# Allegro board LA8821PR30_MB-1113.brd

Outline 233.5 x 89.85 mm; copper layers: TOP, GND1, IN1, GND2, IN2, GND3, VCC, IN3, GND4, IN4, GND5, BOTTOM. Coordinates in mm from the lower left corner of the outline.

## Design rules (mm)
net group SPACING-15-20: nets DMI_IRCOMP RBIAS_CPY
net group 4: nets +1.35V +VREFCA_B GND
net group 10: nets +0.675VS +VREFCA_A +VREFDQ_A +VREFDQ_B
net group DDR_CLK_16_25: nets M_CLK_DDR0 M_CLK_DDR2 M_CLK_DDR#0 M_CLK_DDR#2
net group DDR_CMD_6_16_25: nets DDR3_DRAMRST# DDR_A_BS0 DDR_A_BS1 DDR_A_BS2 DDR_A_CAS# DDR_A_MA0 DDR_A_MA1 DDR_A_MA2 DDR_A_MA3 DDR_A_MA4 DDR_A_MA5 DDR_A_MA6 DDR_A_MA7 DDR_A_MA8 DDR_A_MA9 DDR_A_MA10 DDR_A_MA11 DDR_A_MA12 DDR_A_MA13 DDR_A_MA14 DDR_A_MA15 DDR_A_RAS# DDR_A_WE# DDR_B_BS0 DDR_B_BS1 DDR_B_BS2 DDR_B_CAS# DDR_B_MA0 DDR_B_MA1 DDR_B_MA2 DDR_B_MA3 DDR_B_MA4 DDR_B_MA5 DDR_B_MA6 DDR_B_MA7 DDR_B_MA8 DDR_B_MA9 DDR_B_MA10 DDR_B_MA11 DDR_B_MA12 DDR_B_MA13 DDR_B_MA14 DDR_B_MA15 DDR_B_RAS# DDR_B_WE#
net group DDR_CTRL_6_16_25: nets DDR_A_CKE0 DDR_A_CS0# DDR_B_CKE0 DDR_B_CS0# M_ODT0 M_ODT2
net group DDR_DQ_6_16_25: nets DDR_A_D0 DDR_A_D1 DDR_A_D2 DDR_A_D3 DDR_A_D4 DDR_A_D5 DDR_A_D6 DDR_A_D7 DDR_A_D8 DDR_A_D9 DDR_A_D10 DDR_A_D11 DDR_A_D12 DDR_A_D13 DDR_A_D14 DDR_A_D15 DDR_A_D16 DDR_A_D17 DDR_A_D18 DDR_A_D19 DDR_A_D20 DDR_A_D21 DDR_A_D22 DDR_A_D23 DDR_A_D24 DDR_A_D25 DDR_A_D26 DDR_A_D27 DDR_A_D28 DDR_A_D29 DDR_A_D30 DDR_A_D31 DDR_A_D32 DDR_A_D33 DDR_A_D34 DDR_A_D35 DDR_A_D36 DDR_A_D37 DDR_A_D38 DDR_A_D39 DDR_A_D40 DDR_A_D41 DDR_A_D42 DDR_A_D43 DDR_A_D44 DDR_A_D45 DDR_A_D46 DDR_A_D47 DDR_A_D48 DDR_A_D49 DDR_A_D50 DDR_A_D51 DDR_A_D52 DDR_A_D53 DDR_A_D54 DDR_A_D55 DDR_A_D56 DDR_A_D57 DDR_A_D58 DDR_A_D59 DDR_A_D60 DDR_A_D61 DDR_A_D62 DDR_A_D63 DDR_B_D0 DDR_B_D1 DDR_B_D2 DDR_B_D3 DDR_B_D4 DDR_B_D5 DDR_B_D6 DDR_B_D7 DDR_B_D8 DDR_B_D9 DDR_B_D10 DDR_B_D11 DDR_B_D12 DDR_B_D13 DDR_B_D14 DDR_B_D15 DDR_B_D16 DDR_B_D17 DDR_B_D18 DDR_B_D19 DDR_B_D20 DDR_B_D21 DDR_B_D22 DDR_B_D23 DDR_B_D24 DDR_B_D25 DDR_B_D26 DDR_B_D27 DDR_B_D28 DDR_B_D29 DDR_B_D30 DDR_B_D31 DDR_B_D32 DDR_B_D33 DDR_B_D34 DDR_B_D35 DDR_B_D36 DDR_B_D37 DDR_B_D38 DDR_B_D39 DDR_B_D40 DDR_B_D41 DDR_B_D42 DDR_B_D43 DDR_B_D44 DDR_B_D45 DDR_B_D46 DDR_B_D47 DDR_B_D48 DDR_B_D49 DDR_B_D50 DDR_B_D51 DDR_B_D52 DDR_B_D53 DDR_B_D54 DDR_B_D55 DDR_B_D56 DDR_B_D57 DDR_B_D58 DDR_B_D59 DDR_B_D60 DDR_B_D61 DDR_B_D62 DDR_B_D63
net group DDR_DQS_16_25: nets DDR_A_DQS0 DDR_A_DQS1 DDR_A_DQS2 DDR_A_DQS3 DDR_A_DQS4 DDR_A_DQS5 DDR_A_DQS6 DDR_A_DQS7 DDR_A_DQS#0 DDR_A_DQS#1 DDR_A_DQS#2 DDR_A_DQS#3 DDR_A_DQS#4 DDR_A_DQS#5 DDR_A_DQS#6 DDR_A_DQS#7 DDR_B_DQS0 DDR_B_DQS1 DDR_B_DQS2 DDR_B_DQS3 DDR_B_DQS4 DDR_B_DQS5 DDR_B_DQS6 DDR_B_DQS7 DDR_B_DQS#0 DDR_B_DQS#1 DDR_B_DQS#2 DDR_B_DQS#3 DDR_B_DQS#4 DDR_B_DQS#5 DDR_B_DQS#6 DDR_B_DQS#7
net group SATA-20(15)-20: nets SATA_PRX_DTX_N0 SATA_PRX_DTX_N0_C SATA_PRX_DTX_P0 SATA_PRX_DTX_P0_C SATA_PTX_DRX_N0 SATA_PTX_DRX_N0_C SATA_PTX_DRX_P0 SATA_PTX_DRX_P0_C
net group SPACING-5-10: nets HDA_BIT_CLK HDA_BITCLK_AUDIO HDA_BITCLK_AUDIO_C HDA_RST# HDA_RST_AUDIO# HDA_SDIN0 HDA_SDOUT HDA_SDOUT_AUDIO HDA_SPKR HDA_SYNC HDA_SYNC_AUDIO HDA_SYNC_R
net group SPACING-10.5(9): nets FDI_FSYNC0 FDI_FSYNC1 FDI_INT FDI_LSYNC0 FDI_LSYNC1
net group SPACING-12: nets BUF_CPU_RST# BUFO_CPU_RST# EC_PECI H_CATERR# H_CPUPWRGD H_CPUPWRGD_R H_PECI H_PM_SYNC H_PROCHOT# H_PROCHOT#_R H_THERMTRIP# H_THERMTRIP#_R PLT_RST#
net group SPACING-13: nets SM_RCOMP0 SM_RCOMP1 SM_RCOMP2
net group SPACING-15: nets +EDP_COM CLK_PCI0 CLK_PCI_LPBACK CLK_PCI_TPM CLKFLEX0 DMI_CRX_PTX_N0 DMI_CRX_PTX_N1 DMI_CRX_PTX_N2 DMI_CRX_PTX_N3 DMI_CRX_PTX_P0 DMI_CRX_PTX_P1 DMI_CRX_PTX_P2 DMI_CRX_PTX_P3 DMI_CTX_PRX_N0 DMI_CTX_PRX_N1 DMI_CTX_PRX_N2 DMI_CTX_PRX_N3 DMI_CTX_PRX_P0 DMI_CTX_PRX_P1 DMI_CTX_PRX_P2 DMI_CTX_PRX_P3 EDP_AUXN EDP_AUXN_C EDP_AUXN_CONN EDP_AUXP EDP_AUXP_C EDP_AUXP_CONN EDP_TXN_P0 EDP_TXN_P0_C EDP_TXN_P0_CONN EDP_TXN_P1 EDP_TXN_P1_C EDP_TXN_P1_CONN EDP_TXP_P0 EDP_TXP_P0_C EDP_TXP_P0_CONN EDP_TXP_P1 EDP_TXP_P1_C EDP_TXP_P1_CONN FDI_CTX_PRX_N0 FDI_CTX_PRX_N1 FDI_CTX_PRX_N2 FDI_CTX_PRX_N3 FDI_CTX_PRX_N4 FDI_CTX_PRX_N5 FDI_CTX_PRX_N6 FDI_CTX_PRX_N7 FDI_CTX_PRX_P0 FDI_CTX_PRX_P1 FDI_CTX_PRX_P2 FDI_CTX_PRX_P3 FDI_CTX_PRX_P4 FDI_CTX_PRX_P5 FDI_CTX_PRX_P6 FDI_CTX_PRX_P7 PCH_DP_AUXN PCH_DP_AUXN_C PCH_DP_AUXP PCH_DP_AUXP_C PCH_DP_N0 PCH_DP_N0_C PCH_DP_N1 PCH_DP_N1_C PCH_DP_N2 PCH_DP_N2_C PCH_DP_N3 PCH_DP_N3_C PCH_DP_P0 PCH_DP_P0_C PCH_DP_P1 PCH_DP_P1_C PCH_DP_P2 PCH_DP_P2_C PCH_DP_P3 PCH_DP_P3_C PCH_RTCRST# PCH_RTCX1 PCH_RTCX2 PCH_SRTCRST# PCIE_PRX_WLANTX_N3 PCIE_PRX_WLANTX_P3 PCIE_PTX_WLANRX_N3 PCIE_PTX_WLANRX_N3_C PCIE_PTX_WLANRX_P3 PCIE_PTX_WLANRX_P3_C PEG_COMP SATA3_COMP SATA_COMP SW_USB20_N1 SW_USB20_P1 USB20_N0_CONN USB20_N1 USB20_N4_R USB20_N9 USB20_N12 USB20_N13 USB20_P0_CONN USB20_P1 USB20_P4_R USB20_P9 USB20_P12 USB20_P13 USBRBIAS
net group SPACING-18(12): nets H_CPU_SVIDALRT# H_CPU_SVIDCLK H_CPU_SVIDDAT VR_SVID_ALRT# VR_SVID_CLK VR_SVID_DAT
net group SPACING-20: nets CLK_LPC_DEBUG CLK_PCI1 CLK_PCI2 CLK_PCI3 CLK_PCI4 CLK_PCI_LPC H_DRAMRST# USB3RN0 USB3RN0_RC_CON USB3RN1 USB3RN1_RC_CON USB3RP0 USB3RP0_RC_CON USB3RP1 USB3RP1_RC_CON USB3TN0 USB3TN0_C USB3TN0_RC_CON USB3TN1 USB3TN1_C USB3TN1_RC_CON USB3TP0 USB3TP0_C USB3TP0_RC_CON USB3TP1 USB3TP1_C USB3TP1_RC_CON VDDPWRGOOD VDDPWRGOOD_R
net group SPACING-20(15): nets CLK_CPU_DMI CLK_CPU_DMI# CLK_CPU_DPLL CLK_CPU_DPLL# CLK_PCIE_MINI1 CLK_PCIE_MINI1#
net group SPCING-3.5(5)-10: nets PCH_SPI_CLK PCH_SPI_CLK_R PCH_SPI_CS# PCH_SPI_SI PCH_SPI_SO

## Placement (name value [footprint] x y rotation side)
C265  -  [C_0402NEW]  221.53 27.32 0 bottom
C276  -  [C_0402NEW]  136.93 64 180 top
C277  -  [C_0402NEW]  136.93 64.88 180 top
C278  -  [C_0402NEW]  148.61 52.03 180 top
C279  -  [C_0402NEW]  148.61 52.92 180 top
C280  -  [C_0402NEW]  137.14 52.05 0 top
C281  -  [C_0402NEW]  137.14 51.16 0 top
C282  -  [C_0402NEW]  146.29 52.87 90 top
C283  -  [C_0402NEW]  146.39 51.14 0 top
C284  -  [C_0402NEW]  136.38 61.32 0 top
C285  -  [C_0402NEW]  139.32 54.07 270 top
C286  -  [C_0402NEW]  145.44 54.06 180 top
C293  -  [C_0603NEW]  139.28 64.3 90 top
C303  -  [C_B2]  219.21 27.32 0 bottom
C352  -  [C_0402NEW]  121.72 53.17 180 top
C355  -  [C_0603NEW]  127.76 56.98 270 top
C612  -  [C_0402NEW]  162.2 79.59 180 top
C613  -  [C_0402NEW]  163.89 85.27 270 top
C617  -  [C_0402NEW]  181.24 70.88 0 top
C621  -  [C_0402NEW]  223.6 25.33 270 bottom
C623  -  [C_0402NEW]  222.71 25.33 270 bottom
C654  -  [C_0402NEW]  141.28 64.26 90 top
C655  -  [C_0402NEW]  53.78 84.83 90 top
C656  -  [C_0402NEW]  50.32 84.92 180 top
C707  -  [C_0603NEW]  177.35 36.74 270 top
C708  -  [C_0402NEW]  179.64 36.95 90 top
C709  -  [C_0402NEW]  179.6 43.9 180 top
C710  -  [C_0402NEW]  179.73 26.38 180 top
C711  -  [C_0402NEW]  178.62 36.63 270 top
C712  -  [C_0603NEW]  177.35 43.7 90 top
C713  -  [C_0402NEW]  180.22 49.68 90 top
C714  -  [C_0402NEW]  179.64 36 270 top
C715  -  [C_0402NEW]  178.67 25.46 270 top
C716  -  [C_0402NEW]  179.64 33.01 90 top
C719  -  [C_0603NEW]  168.58 69.4 270 top
C720  -  [C_0402NEW]  167.31 69.41 270 top
C721  -  [C_0402NEW]  168.71 57.08 270 top
C722  -  [C_0402NEW]  175.85 51.17 0 top
C961  -  [C_0402NEW]  207.83 54.44 0 top
C962  -  [C_0603NEW]  212.07 64.27 0 top
C963  -  [C_0402NEW]  212.31 63.06 0 top
C964  -  [C_0402NEW]  154.67 47.93 270 top
C965  -  [C_0402NEW]  156.69 47.95 270 top
C966  -  [C_0402NEW]  155.67 47.95 270 top
C968  -  [C_0603NEW]  150.81 55.77 90 top
C969  -  [C_0603NEW]  139.26 79.88 90 top
C970  -  [C_0603NEW]  140.48 79.88 90 top
C974  -  [C_0402NEW]  141.92 81.11 90 top
C976  -  [C_0402NEW]  158.01 60.16 180 top
C977  -  [C_0402NEW]  163.51 60.05 0 top
C978  -  [C_0402NEW]  156.01 61.02 270 top
C979  -  [C_0402NEW]  163.51 60.93 0 top
C1059  -  [C_0603NEW]  169.29 32.98 180 bottom
C1060  -  [C_0402NEW]  163.52 73.29 90 bottom
C1061  -  [C_0402NEW]  165.43 73.29 90 bottom
C1062  -  [C_0402NEW]  162.63 73.29 90 bottom
C1063  -  [C_0402NEW]  164.54 73.29 90 bottom
C1064  -  [C_0402NEW]  160.84 73.32 90 bottom
C1065  -  [C_0402NEW]  159.95 73.32 90 bottom
C1078  -  [C_0402NEW]  162.87 30.49 90 top
C1098  -  [C_0402NEW]  13.04 19.9 0 top
C1099  -  [C_0402NEW]  14.03 23.74 90 top
C1100  -  [C_0402NEW]  13.04 19.01 0 top
C1101  -  [C_0402NEW]  16.03 24.85 180 top
C1102  -  [C_0402NEW]  9.11 20.41 180 top
C1107  -  [C_0402NEW]  202.66 56.05 0 bottom
C1108  -  [C_0402NEW]  202.66 55.16 0 bottom
C1109  -  [C_B2]  216.82 64.6 0 bottom
C1110  -  [C_0402NEW]  215.45 50.25 270 bottom
C1116  -  [C_0402NEW]  136.36 54.06 0 top
C1117  -  [C_0402NEW]  144.84 64.26 90 top
C1118  -  [C_0402NEW]  151.57 61.14 270 top
C1122  -  [C_0402NEW]  228.91 21.42 180 top
C1123  -  [C_0402NEW]  24.98 20.92 0 top
C1124  -  [C_0402NEW]  25.93 22.69 180 top
C1125  -  [C_0402NEW]  18.39 24.88 180 top
C1133  -  [C_0402NEW]  182.15 78.5 0 top
C1135  -  [C_0402NEW]  158.68 47.71 270 top
C1136  -  [C_0402NEW]  157.79 47.71 270 top
C1137  -  [C_0402NEW]  154.85 68.05 270 top
C1138  -  [C_0402NEW]  133.37 78.96 180 bottom
C1139  -  [C_0402NEW]  167.75 52.63 270 top
C1140  -  [C_0402NEW]  167.82 56.13 90 top
C1141  -  [C_0402NEW]  156.97 56.48 0 top
C1142  -  [C_0402NEW]  177.15 77.89 270 top
C1143  -  [C_0603NEW]  180.25 77.93 270 top
C1145  -  [C_0402NEW]  178.92 77.89 270 top
C1146  -  [C_0402NEW]  13.04 20.79 0 top
C1151  -  [C_0402NEW]  159.06 78.7 180 top
C1152  -  [C_0402NEW]  153 67.53 0 top
C1153  -  [C_0603NEW]  165.48 32.98 0 bottom
C1154  -  [C_0402NEW]  134.22 21.68 180 top
C1155  -  [C_0402NEW]  138.36 24.6 270 top
C1156  -  [C_0402NEW]  138.11 22.14 270 top
C1157  -  [C_0402NEW]  141.54 25.36 0 top
C1158  -  [C_0402NEW]  182.15 77.61 0 top
C1159  -  [C_0603NEW]  181.46 76.54 0 top
C1160  -  [C_0402NEW]  167.32 35.43 90 bottom
C1161  -  [C_0402NEW]  173.83 63.59 0 top
C1162  -  [C_0603NEW]  170.49 68.49 270 top
C1163  -  [C_0402NEW]  174.17 69.84 90 top
C1164  -  [C_0402NEW]  175.06 69.84 90 top
C1165  -  [C_0603NEW]  176.33 67.35 270 top
C1167  -  [C_0402NEW]  169.73 51.9 270 top
C1168  -  [C_0402NEW]  177.98 54.06 0 top
C1169  -  [C_0402NEW]  176.37 53.17 0 top
C1170  -  [C_0402NEW]  176.37 52.29 0 top
C1171  -  [C_0603NEW]  175.7 50.2 270 top
C1172  -  [C_0603NEW]  210.12 63.16 180 top
C1173  -  [C_0402NEW]  209.91 64.43 180 top
C1174  -  [C_0402NEW]  166.43 30.49 90 top
C1175  -  [C_0402NEW]  165.54 30.49 90 top
C1176  -  [C_0402NEW]  164.65 30.49 90 top
C1177  -  [C_0402NEW]  163.76 30.49 90 top
C1178  -  [C_0402NEW]  169.98 30.49 90 top
C1179  -  [C_0402NEW]  169.09 30.49 90 top
C1180  -  [C_0402NEW]  168.21 30.49 90 top
C1181  -  [C_0402NEW]  167.32 30.49 90 top
C1182  -  [C_0402NEW]  158.43 30.49 90 top
C1183  -  [C_0402NEW]  157.54 30.49 90 top
C1184  -  [C_0402NEW]  156.65 30.49 90 top
C1185  -  [C_0402NEW]  155.76 30.49 90 top
C1186  -  [C_0402NEW]  151.31 30.49 90 top
C1187  -  [C_0402NEW]  150.43 30.49 90 top
C1188  -  [C_0402NEW]  149.41 29.35 90 top
C1189  -  [C_0402NEW]  148.52 29.35 90 top
C1190  -  [C_0402NEW]  154.87 30.49 90 top
C1191  -  [C_0402NEW]  153.98 30.49 90 top
C1192  -  [C_0402NEW]  153.09 30.49 90 top
C1193  -  [C_0402NEW]  152.2 30.49 90 top
C1194  -  [C_0402NEW]  161.98 30.49 90 top
C1195  -  [C_0402NEW]  161.09 30.49 90 top
C1196  -  [C_0402NEW]  160.2 30.49 90 top
C1197  -  [C_0402NEW]  159.32 30.49 90 top
C1198  -  [C_0402NEW]  171.41 76.42 0 bottom
C1199  -  [C_0402NEW]  174.63 78.3 0 top
C1200  -  [C_0402NEW]  169.74 79.57 90 top
C1204  -  [C_0402NEW]  160.81 67.83 180 top
C1205  -  [C_0402NEW]  162.14 67.83 0 top
C1206  -  [C_0402NEW]  178.44 74.42 180 bottom
C1207  -  [C_0402NEW]  157.42 74.07 270 top
CC65  -  [C_0402NEW]  144.2 47.68 270 top
CC68  -  [C_0402NEW]  130.41 77.91 90 bottom
CC69  -  [C_0402NEW]  50.86 51.43 90 top
CC138  -  [C_0603NEW]  65.3 48.36 180 bottom
CC139  -  [C_0603NEW]  77.78 50.14 0 bottom
CC160  -  [C_0603NEW]  61.14 67.46 90 top
CC161  -  [C_0603NEW]  71.43 67.46 90 top
CC162  -  [C_0603NEW]  71.41 61.62 90 top
CC163  -  [C_0603NEW]  72.63 61.62 90 top
CC164  -  [C_0603NEW]  61.21 59.02 180 top
CC165  -  [C_0603NEW]  60.95 56.86 180 top
CC166  -  [C_B2]  66.6 50.78 0 bottom
CC167  -  [C_0603NEW]  93.43 82.46 270 bottom
CC168  -  [C_0603NEW]  93.43 83.83 90 bottom
CC169  -  [C_0603NEW]  93.81 83.71 90 top
CC170  -  [C_0603NEW]  93.91 81.95 270 top
CC171  -  [C_B2]  86.01 84.29 0 bottom
CC172  -  [C_0603NEW]  81.08 53.64 270 bottom
CC174  -  [C_0402NEW]  85.54 55.38 90 bottom
CC175  -  [C_0402NEW]  86.43 55.38 90 bottom
CC176  -  [C_D2]  84.26 52.21 270 bottom
CC181  -  [C_0402NEW]  69.03 47.64 90 bottom
CC182  -  [C_0402NEW]  67.26 47.64 90 bottom
CC183  -  [C_0402NEW]  66.37 47.64 90 bottom
CC184  -  [C_0402NEW]  68.15 47.64 90 bottom
CC217  -  [C_0402NEW]  76.73 46.32 180 bottom
CC218  -  [C_0402NEW]  61.11 60.54 180 top
CC219  -  [C_0402NEW]  72.72 83.45 90 top
CC220  -  [C_0402NEW]  73.61 83.45 90 top
CC221  -  [C_0402NEW]  75.56 67.46 270 top
CC222  -  [C_0402NEW]  78.56 68.65 270 top
CC223  -  [C_0402NEW]  74 60.29 0 top
CC224  -  [C_0402NEW]  70.3 64.46 270 top
CC225  -  [C_0603NEW]  84.7 74.5 0 top
CC226  -  [C_0402NEW]  76.38 71.68 270 top
CC227  -  [C_0402NEW]  72.07 75.81 90 top
CC228  -  [C_0402NEW]  71.18 75.81 90 top
CC229  -  [C_0402NEW]  75.11 80 90 top
CC230  -  [C_0402NEW]  76 80 90 top
CC231  -  [C_0603NEW]  73.78 57.87 0 top
CC232  -  [C_0603NEW]  73.78 59.14 0 top
CC233  -  [C_0402NEW]  62.29 67.7 90 top
CC234  -  [C_0402NEW]  63.18 67.7 90 top
CC235  -  [C_0402NEW]  64.07 67.7 90 top
CC236  -  [C_0402NEW]  64.95 67.7 90 top
CC237  -  [C_0402NEW]  65.84 67.7 90 top
CC238  -  [C_0402NEW]  66.73 67.7 90 top
CC239  -  [C_0402NEW]  67.62 67.7 90 top
CC240  -  [C_0402NEW]  68.51 67.7 90 top
CC241  -  [C_0402NEW]  69.4 67.7 90 top
CC242  -  [C_0402NEW]  70.29 67.7 90 top
CD1  -  [C_0402NEW]  33.74 46.02 90 bottom
CD2  -  [C_0603NEW]  72.27 19.52 180 top
CD3  -  [C_0402NEW]  99.08 20.03 180 top
CD4  -  [C_0603NEW]  87.81 38.24 90 top
CD5  -  [C_0402NEW]  88.81 20.3 180 top
CD6  -  [C_0603NEW]  79.18 38.37 90 bottom
CD7  -  [C_0402NEW]  76.8 20.28 0 bottom
CD8  -  [C_0603NEW]  72.3 19.6 180 bottom
CD29  -  [C_0402NEW]  76.8 20.28 0 top
CD30  -  [C_0603NEW]  53.39 41.8 180 top
CD33  -  [C_0402NEW]  98.13 20.03 0 bottom
CD34  -  [C_0603NEW]  105.42 20.03 180 bottom
CD37  -  [C_0402NEW]  91.93 38.53 90 top
CD38  -  [C_0603NEW]  87.81 38.24 90 bottom
CD41  -  [C_0402NEW]  91.7 38.5 90 bottom
CD42  -  [C_0603NEW]  105.02 20.45 270 top
CD57  -  [C_0402NEW]  33.49 41.87 0 top
CD58  -  [C_0603NEW]  32.39 42.25 180 top
CD59  -  [C_0402NEW]  55.81 41.52 0 top
CD60  -  [C_0603NEW]  32.47 45.71 90 bottom
CD61  -  [C_0402NEW]  59.62 44.19 90 bottom
CD62  -  [C_0603NEW]  79.18 38.37 90 top
CD63  -  [C_0402NEW]  88.81 20.3 180 bottom
CD64  -  [C_0603NEW]  42.04 42.25 180 top
CD85  -  [C_0402NEW]  49.88 46.13 90 bottom
CD86  -  [C_0603NEW]  48.83 45.86 90 bottom
CD87  -  [C_0402NEW]  43.14 41.87 0 top
CD88  -  [C_0603NEW]  26.32 43.35 90 bottom
CD89  -  [C_0402NEW]  27.36 43.6 90 bottom
CD90  -  [C_0603NEW]  23.88 42.25 180 top
CD91  -  [C_0402NEW]  25.11 41.87 0 top
CD92  -  [C_0603NEW]  58.35 44.08 90 bottom
CD113  -  [C_0402NEW]  112.85 20.17 270 top
CD114  -  [C_0402NEW]  111.96 20.17 270 top
CD115  -  [C_0402NEW]  18.07 41.63 180 top
CD116  -  [C_0402NEW]  18.07 42.52 180 top
CD117  -  [C_0402NEW]  114.37 36.46 90 top
CD118  -  [C_0402NEW]  115.26 36.46 90 top
CD119  -  [C_0402NEW]  17.82 39.33 180 bottom
CD120  -  [C_0402NEW]  17.82 38.44 180 bottom
CD121  -  [C_0402NEW]  66.33 28.99 270 bottom
CD122  -  [C_0402NEW]  66.17 34.52 270 bottom
CD123  -  [C_0402NEW]  119.79 34.51 180 top
CD124  -  [C_0402NEW]  16.82 35.81 90 bottom
CD125  -  [C_B2]  93.99 38.19 270 bottom
CD126  -  [C_B2]  37.88 44.74 270 bottom
CD127  -  [C_0402NEW]  70.07 52.29 0 top
CD128  -  [C_0402NEW]  80.7 53.14 270 top
CD129  -  [C_0402NEW]  120.27 28.17 0 top
CD132  -  [C_0402NEW]  120.27 26.39 0 top
CD133  -  [C_0402NEW]  120.27 27.28 0 top
CD135  -  [C_0402NEW]  120.27 29.06 0 top
CD136  -  [C_0402NEW]  15.17 29.65 270 top
CD139  -  [C_0402NEW]  15.17 27.74 270 top
CD140  -  [C_0402NEW]  15.28 39.86 180 top
CD142  -  [C_0402NEW]  15.28 38.97 180 top
CH2  -  [C_0402NEW]  119.87 62.95 270 top
CH3  -  [C_0402NEW]  119.87 63.83 90 top
CH4  -  [C_0402NEW]  123.17 57.47 180 top
CH5  -  [C_0402NEW]  120.07 64.6 270 bottom
CH6  -  [C_0402NEW]  124.12 85.12 0 bottom
CH11  -  [C_0402NEW]  176.59 39.97 180 bottom
CH16  -  [C_0402NEW]  176.59 40.86 180 bottom
CH21  -  [C_0402NEW]  121.47 80.23 0 top
CH22  -  [C_0402NEW]  123.58 77.85 90 bottom
CH23  -  [C_0402NEW]  112.78 78.59 270 top
CH24  -  [C_0402NEW]  112.78 79.55 90 top
CH25  -  [C_0402NEW]  107.75 64.7 270 top
CH26  -  [C_0402NEW]  106.86 64.7 270 top
CH27  -  [C_0805NEW]  104.45 43.22 270 top
CH28  -  [C_0402NEW]  105.98 64.7 270 top
CH35  -  [C_0805NEW]  99.77 58.42 270 top
CH36  -  [C_0402NEW]  110.67 71.88 90 top
CH37  -  [C_0805NEW]  88.52 47.19 90 bottom
CH38  -  [C_0402NEW]  102.58 66 0 top
CH39  -  [C_0402NEW]  101.62 66 180 top
CH40  -  [C_0402NEW]  100.9 62.99 90 top
CH41  -  [C_0402NEW]  100.74 69.81 180 top
CH42  -  [C_0402NEW]  100.9 62.03 270 top
CH43  -  [C_0402NEW]  103.04 71.78 0 top
CH44  -  [C_0402NEW]  96.48 67.27 0 top
CH45  -  [C_0402NEW]  105.85 60.63 270 top
CH46  -  [C_0402NEW]  102.89 61.3 180 top
CH47  -  [C_0402NEW]  108.64 63.75 90 top
CH48  -  [C_0402NEW]  110.8 60.51 270 top
CH49  -  [C_0603NEW]  95.13 70.19 180 top
CH50  -  [C_0402NEW]  111.22 65.11 0 top
CH51  -  [C_0402NEW]  111.98 59.5 0 top
CH52  -  [C_0402NEW]  110.77 66.89 180 top
CH53  -  [C_0402NEW]  111.85 66.89 0 top
CH54  -  [C_0402NEW]  109.73 60.57 270 top
CH55  -  [C_0402NEW]  101.64 68.48 0 top
CH56  -  [C_0402NEW]  112.87 71.21 0 top
CH57  -  [C_0805NEW]  102.55 43.22 270 top
CH58  -  [C_0805NEW]  100.64 43.22 270 top
CH59  -  [C_0402NEW]  104.81 66.7 0 top
CH60  -  [C_0402NEW]  107.12 66.86 270 top
CH61  -  [C_0402NEW]  108.01 66.86 270 top
CH62  -  [C_0402NEW]  108.9 66.86 270 top
CH63  -  [C_0402NEW]  112.36 70.07 0 top
CH64  -  [C_0402NEW]  111.91 70.95 180 top
CH65  -  [C_0402NEW]  107.63 62.79 270 top
CH66  -  [C_0603NEW]  129.9 65.62 0 top
CH67  -  [C_0402NEW]  109.75 70.95 180 top
CH68  -  [C_0402NEW]  111.6 72.22 0 top
CH69  -  [C_0402NEW]  105.85 57.98 90 top
CH70  -  [C_0402NEW]  105.75 61.56 0 top
CH71  -  [C_0402NEW]  110.46 61.49 180 top
CH72  -  [C_0402NEW]  105.5 62.57 0 top
CH73  -  [C_0603NEW]  98.38 54.83 270 top
CH74  -  [C_0402NEW]  107.85 71.08 180 top
CH75  -  [C_0402NEW]  108.59 61.78 90 top
CH76  -  [C_0402NEW]  102.27 69.37 0 top
CH77  -  [C_0402NEW]  107.85 70.19 180 top
CH78  -  [C_0402NEW]  110.46 62.38 180 top
CH79  -  [C_0603NEW]  104.2 62.32 270 top
CH80  -  [C_0402NEW]  103.82 63.37 90 top
CH81  -  [C_0402NEW]  102.93 63.37 90 top
CH82  -  [C_0402NEW]  113.47 62.03 270 top
CH83  -  [C_0402NEW]  112.58 62.03 270 top
CH84  -  [C_0402NEW]  111.69 62.03 270 top
CH85  -  [C_0402NEW]  109.02 69.65 270 top
CH86  -  [C_B2]  89.02 73.29 180 bottom
CH87  -  [C_0402NEW]  97.59 72 90 top
CH88  -  [C_B2]  88.89 67.9 90 bottom
CH89  -  [C_0402NEW]  98.86 72.1 270 top
CH94  -  [C_0402NEW]  140.16 80.48 0 bottom
CH95  -  [C_0402NEW]  27.48 46.77 90 bottom
CH99  -  [C_0402NEW]  118.2 78.7 0 top
CH102  -  [C_0402NEW]  116.03 51.43 90 bottom
CH103  -  [C_0402NEW]  115.03 71.34 0 top
CH107  -  [C_0402NEW]  120.56 78.09 90 bottom
CH116  -  [C_0402NEW]  133.03 64.19 270 top
CH117  -  [C_0402NEW]  116.36 65.75 180 top
CH118  -  [C_0402NEW]  106.99 56 90 top
CH1202  -  [C_0402NEW]  157.5 68.03 0 top
CH1203  -  [C_0402NEW]  156.66 68.03 180 top
CLRP1  -  [SHORTPADS]  122.74 56.35 180 top
CLRP2  -  [SHORTPADS]  118.04 66 180 top
CRF1  -  [C_0402NEW]  159.87 29.11 0 bottom
CRF2  -  [C_0402NEW]  160.79 26.06 180 bottom
CRF3  -  [C_0402NEW]  154.49 25.03 180 bottom
CRF4  -  [C_0402NEW]  162.55 27.06 90 bottom
CRF5  -  [C_0402NEW]  158.62 27.05 180 bottom
CS42  -  [C_0402NEW]  181 52.79 180 bottom
CS43  -  [C_0402NEW]  181 53.68 180 bottom
CS53  -  [C_0402NEW]  180.87 55.08 180 bottom
CS54  -  [C_0402NEW]  180.87 55.97 180 bottom
CV1  -  [C_0603NEW]  208.08 73.56 270 bottom
CV2  -  [C_0402NEW]  210.12 73.57 270 bottom
CV3  -  [C_0402NEW]  216.31 73.49 180 top
CV4  -  [C_0402NEW]  216.31 74.38 180 top
CV5  -  [C_0402NEW]  216.31 72.61 180 top
CV6  -  [C_0402NEW]  214.23 69.35 90 bottom
CV7  -  [C_0402NEW]  216.31 71.72 180 top
CV8  -  [C_0402NEW]  168.81 60.41 180 top
CV9  -  [C_0402NEW]  213.34 69.35 90 bottom
CV10  -  [C_0402NEW]  168.81 59.52 180 top
CV11  -  [C_0402NEW]  214.53 66.66 180 bottom
CV12  -  [C_0402NEW]  214.53 67.55 180 bottom
CV13  -  [C_0402NEW]  178.75 61.65 270 top
CV14  -  [C_0402NEW]  209.23 73.57 270 bottom
CV15  -  [C_0805NEW]  205.25 75.01 180 top
D50  -  [IP4223CZ6_SO6]  180.48 76.46 0 bottom
D72  -  [SDMK0340L-7-F_SOD323-2]  164.52 74.64 0 top
D73  -  [SDMK0340L-7-F_SOD323-2]  160.02 74.64 0 top
D74  -  [LXES4XBAA6-027_MSOP8]  220.83 21.36 270 bottom
D81  -  [SDMK0340L-7-F_SOD323-2]  8.59 22.44 180 top
D82  -  [LXES4XBAA6-027_MSOP8]  211.24 56.39 90 bottom
D83  -  [BAT54CW-7-F_SOT323-3]  139.82 69.94 270 top
D84  -  [RB751V-40GTE-17_SOD323-2]  149.88 62.62 0 top
D85  -  [RB751V-40GTE-17_SOD323-2]  133.79 59.94 270 top
D90  -  [IP4223CZ6_SO6]  155.95 76.19 0 bottom
D92  -  [SDMK0340L-7-F_SOD323-2]  160.02 76.42 0 top
D93  -  [BAT54CW-7-F_SOT323-3]  168.77 65.37 270 top
DE1  -  [PESD5V0U2BT_SOT23-3]  142.3 22.57 90 top
DE2  -  [PESD5V0U2BT_SOT23-3]  126.93 25.87 270 top
DH2  -  [RB751S40T1_SOD523-2]  128.59 67.39 0 top
DH3  -  [RB751S40T1_SOD523-2]  128.96 70.38 270 top
DH4  -  [BAT54CW-7-F_SOT323-3]  29.17 45.48 0 bottom
DV1  -  [D_RCLAMP0524PPTCT]  217.68 73.61 270 top
DV2  -  [D_RCLAMP0524PPTCT]  216.9 68.78 270 bottom
F1  -  [F_1812L075-24DR]  163 34 180 bottom
FD1  -  [FIDUCIAL_C40M80]  227.59 26.35 180 bottom
FD2  -  [FIDUCIAL_C40M80]  13.34 36.99 180 bottom
FD3  -  [FIDUCIAL_C40M80]  199.91 75.27 180 bottom
FD4  -  [FIDUCIAL_C40M80]  227.59 26.35 0 top
FD5  -  [FIDUCIAL_C40M80]  199.94 76.09 0 top
FD6  -  [FIDUCIAL_C40M80]  3.21 25.15 0 top
FV1  -  [F_1206L150PR]  206.99 76.75 270 top
H1  -  [H_2P3]  217 79.25 0 top
H3  -  [H_4P0]  10.8 31.75 0 top
H5  -  [H_2P3]  226 17.35 0 top
H6  -  [H_2P3]  147.5 86.83 0 top
H7  -  [H_2P3]  77.5 86.83 0 top
H8  -  [H_2P3]  144.1 31.85 0 top
H9  -  [H_3P2]  43.65 78.93 0 top
H10  -  [H_3P2]  43.65 60.03 0 top
H11  -  [H_3P2]  89.15 78.93 0 top
H12  -  [H_3P2]  89.15 60.03 0 top
H13  -  [H_4P5N]  123.6 69.52 0 top
H14  -  [H_3P2]  58.5 13.75 0 top
H16  -  [H_2P0X2P5N]  17.75 86.83 90 top
H17  -  [H_2P0N]  171 86.83 0 top
H19  -  [EMI-79X138]  180.4 59.35 270 bottom
H20  -  [EMI-79X138]  211.4 53.34 270 bottom
H21  -  [EMI-79X138]  208.11 77.24 90 bottom
JANT1  -  [HRS_UPFL-R-SMT-1-10_3P]  166.16 24.25 180 bottom
JANT2  -  [HRS_UPFL-R-SMT-1-10_3P]  160.17 23.23 180 bottom
JANT3  -  [HRS_UPFL-R-SMT-1-10_3P]  154.16 22.24 180 bottom
JBATT9  -  [FOX_GS73091-10272-7H_9P-T]  116.87 21.88 180 bottom
JBL1  -  [ACES_50519-00401-P01_4P-T]  174.45 29.87 180 bottom
JDCIN1  -  [ACES_50281-00501-001_5P-T]  191.72 83.16 270 bottom
JFAN1  -  [ACES_50281-0040N-001_4P]  8.56 25.24 90 bottom
JIOL1  -  [E-T_1001-F36E-03R_36P]  14.1 19.92 0 bottom
JKB1  -  [ACES_50699-03041-001_30P-T]  146.1 27.85 0 top
JLVDS1  -  [ACES_50406-02071-001_20P]  166.25 79.69 180 bottom
JLVDS2  -  [ACES_50406-02071-001_20P]  185.24 79.69 180 bottom
JMDP1  -  [ACON_MAR2B-20K1200_20P-T]  223.66 74.3 270 bottom
JP1  -  [JUMP_43X39]  175.78 35.9 180 top
JRTC1  -  [ACES_50271-00201-001_2P]  22.68 51.54 180 bottom
JSATA1  -  [TYCO_2041119-1_52P]  175.75 69.22 270 bottom
JTP1  -  [TYCO_2041084-6_6P]  143.25 27.81 0 bottom
JUSB1  -  [TAIWI_USB014-107CRL-TW_10P-T]  217.42 33.6 270 bottom
JUSB2  -  [ACON_TARAG-9V1391_9P-T]  219 52.1 270 bottom
JWLAN1  -  [BELLW_80019-1021_52P]  180.05 24.55 270 bottom
L40  -  [SW_WCM2012F2S_4P]  216.98 24.48 270 bottom
L43  -  [KC_FBMA-L11-160808-800LMT_2P]  143.71 51.14 0 top
L44  -  [KC_FBMA-L11-160808-800LMT_2P]  143.71 52.67 0 top
L45  -  [MURAT_DLW21SN670HQ2L_4P]  223.62 23.16 270 bottom
L46  -  [MURAT_DLW21SN670HQ2L_4P]  219.81 24.48 270 bottom
L49  -  [SW_WCM2012F2S_4P]  174.64 38.13 0 bottom
L52  -  [SW_WCM2012F2S_4P]  211.65 59.63 0 bottom
L53  -  [MURAT_DLW21SN670HQ2L_4P]  204.95 56.11 0 bottom
L54  -  [MURAT_DLW21SN670HQ2L_4P]  204.95 54.21 0 bottom
L55  -  [SW_WCM2012F2S_4P]  177.32 75.83 0 bottom
L56  -  [MURAT_DLW21SN670HQ2L_4P]  164.54 75.31 90 bottom
L57  -  [MURAT_DLW21SN670HQ2L_4P]  162.63 75.31 90 bottom
L58  -  [MURAT_DLW21SN670HQ2L_4P]  159.95 75.35 90 bottom
L59  -  [MURAT_BLM18AG601SN1D_L0603_2P]  136.96 21.21 90 top
L60  -  [MURAT_BLM18AG601SN1D_L0603_2P]  139.38 25.36 0 top
LED1  -  [LED_27-11-T1D-CP1Q1RY-3C_2P]  231.5 17.35 270 top
LED2  -  [LED_27-11-T1D-CP1Q1RY-3C_2P]  231.5 13.75 270 top
LED3  -  [LED_27-11-T1D-CP1Q1RY-3C_2P]  231.5 10.15 270 top
LED4  -  [LED_27-11-T1D-CP1Q1RY-3C_2P]  231.5 6.55 270 top
LED5  -  [LED_27-11-T1D-CP1Q1RY-3C_2P]  231.5 2.94 270 top
LH3  -  [MURAT_LQM21FN1R0N00D_2P]  96.72 58.38 0 top
LH4  -  [MURAT_LQM21FN100M80L_2P]  93.69 71.97 0 top
LH6  -  [MURAT_LQM21FN100M80L_2P]  96.72 54.99 270 top
LH7  -  [MURAT_LQM21FN100M80L_2P]  86.54 72.24 90 bottom
LH8  -  [MURAT_LQM21FN100M80L_2P]  87.74 70.47 0 bottom
LH9  -  [MURAT_BLM18BA220SN1D_2P]  14.15 27.61 270 bottom
NOREF  -  []  58.5 13.75 0 top
NOREF#2  -  []  89.15 78.93 0 top
NOREF#3  -  []  26.85 50.53 0 top
NOREF#4  -  []  147.5 86.83 0 top
NOREF#5  -  []  10.8 31.75 0 top
NOREF#6  -  []  77.5 86.83 0 top
NOREF#7  -  []  43.65 60.03 0 top
NOREF#8  -  []  89.15 60.03 0 top
NOREF#9  -  []  18.73 73.94 0 top
NOREF#10  -  []  100.77 -24.21 0 top
NOREF#11  -  []  43.65 78.93 0 top
NOREF#12  -  []  226 17.35 0 top
NOREF#13  -  []  33.94 132.11 0 top
NOREF#14  -  []  83.75 50.63 0 top
NOREF#15  -  []  31.87 49.22 0 top
NOREF#16  -  []  217 79.25 0 top
NOREF#17  -  []  144.1 31.85 0 top
NOREF#18  -  []  -19.4 53.03 180 bottom
NOREF#19  -  []  33.46 56.16 180 bottom
NOREF#20  -  []  36.44 52.52 180 bottom
NOREF#21  -  []  80.7 41.26 180 bottom
PC15  -  [C_0805NEW]  133.87 39.08 180 top
PC16  -  [C_0805NEW]  133.87 40.98 180 top
PC17  -  [C_0805NEW]  131.99 35.47 90 top
PC18  -  [C_0805NEW]  133.87 42.89 180 top
PC19  -  [C_0402NEW]  146.03 38.96 0 top
PC20  -  [C_0402NEW]  144.58 39.98 270 top
PC21  -  [C_0402NEW]  146.98 38.07 180 top
PC22  -  [C_0402NEW]  143.42 37.37 270 bottom
PC23  -  [C_0402NEW]  147.84 39.74 270 top
PC24  -  [C_0805NEW]  134.4 40.98 180 bottom
PC25  -  [C_0402NEW]  129.8 32.52 270 top
PC26  -  [C_0805NEW]  136.58 39.2 0 bottom
PC27  -  [C_0805NEW]  128.05 37.43 0 top
PC28  -  [C_0805NEW]  126.65 37.35 180 top
PC29  -  [C_0402NEW]  151.65 32.66 90 bottom
PC30  -  [C_0402NEW]  129.85 29.27 270 top
PC31  -  [C_0402NEW]  148.55 33.41 0 top
PC32  -  [C_0603NEW]  149.03 33.19 270 bottom
PC33  -  [C_0402NEW]  150.98 40.91 90 bottom
PC34  -  [C_0603NEW]  150.17 35.39 90 top
PC35  -  [C_0402NEW]  149.6 38.84 180 top
PC36  -  [C_0402NEW]  153.41 39.64 90 bottom
PC37  -  [C_0402NEW]  149.79 37.74 0 top
PC38  -  [C_0402NEW]  152.57 38.77 0 bottom
PC39  -  [C_0402NEW]  146.72 40.91 90 bottom
PC41  -  [C_0402NEW]  163.22 45.24 180 top
PC43  -  [C_0805NEW]  134.4 39.08 180 bottom
PC44  -  [C_0805NEW]  136.63 41.11 0 bottom
PC45  -  [C_0402NEW]  159.53 44.35 0 top
PC124  -  [C_0603NEW]  50.17 83.86 180 top
PC125  -  [C_0603NEW]  200.9 57.71 270 top
PC201  -  [C_0402NEW]  195.89 66.48 180 top
PC202  -  [C_0402NEW]  198.89 66.64 0 top
PC203  -  [C_0805NEW]  195.71 64.3 180 top
PC204  -  [C_0805NEW]  197.73 64.35 0 top
PC205  -  [C_0805NEW]  197.58 53.81 0 bottom
PC206  -  [C_0402NEW]  195.89 65.6 180 top
PC207  -  [C_0402NEW]  198.89 65.75 0 top
PC208  -  [C_0603NEW]  188.06 55.97 0 top
PC209  -  [C_0603NEW]  197.61 54.83 0 top
PC210  -  [C_B2]  184.18 64.86 270 bottom
PC212  -  [C_0603NEW]  191 65.37 0 top
PC213  -  [C_0603NEW]  204.08 66.13 180 top
PC214  -  [C_B2]  186.67 62.03 90 bottom
PC215  -  [C_0603NEW]  182.94 55.27 90 top
PC216  -  [C_0402NEW]  191.52 55 90 bottom
PC217  -  [C_0603NEW]  186.47 76.8 180 top
PC218  -  [C_0402NEW]  206.18 62.4 270 top
PC219  -  [C_0402NEW]  198.05 57.65 90 top
PC220  -  [C_0402NEW]  189.35 57.33 0 top
PC221  -  [C_0402NEW]  186.47 59.55 90 top
PC222  -  [C_0805NEW]  188.58 77.05 0 top
PC224  -  [C_B2]  203.83 67.27 0 bottom
PC300  -  [C_0805NEW]  45.24 20.98 270 top
PC301  -  [C_0603NEW]  36.38 19.56 180 top
PC302  -  [C_0805NEW]  47.02 20.98 270 top
PC303  -  [C_0402NEW]  27.26 22.31 0 top
PC304  -  [C_0402NEW]  43.9 20.56 270 top
PC305  -  [C_0805NEW]  34.64 22.69 0 bottom
PC306  -  [C_0805NEW]  34.64 20.92 0 bottom
PC307  -  [C_0603NEW]  35.06 19.18 180 bottom
PC308  -  [C_B]  58.91 23.62 270 bottom
PC309  -  [C_0402NEW]  31.55 24.22 270 bottom
PC310  -  [C_0603NEW]  31.49 20.92 0 bottom
PC311  -  [C_0603NEW]  55.96 20.56 270 top
PC312  -  [C_0402NEW]  25.97 24.46 180 top
PC313  -  [C_0402NEW]  28.18 23.18 180 bottom
PC314  -  [C_0402NEW]  27.44 24.02 90 top
PC400  -  [C_0805NEW]  105.47 47.46 180 bottom
PC401  -  [C_0402NEW]  105.26 51.65 0 top
PC402  -  [C_0805NEW]  95.05 51.36 270 top
PC403  -  [C_0805NEW]  94.93 51.87 270 bottom
PC404  -  [C_0402NEW]  102.09 53.94 0 top
PC405  -  [C_0603NEW]  96.2 47.52 270 bottom
PC406  -  [C_0402NEW]  169.4 41.87 0 top
PC407  -  [C_0402NEW]  171.18 39.2 0 top
PC408  -  [C_0805NEW]  160.33 39.12 90 bottom
PC409  -  [C_0603NEW]  165.98 42.38 0 top
PC410  -  [C_0805NEW]  172.9 36.88 270 bottom
PC411  -  [C_0805NEW]  162.11 39.12 90 bottom
PC500  -  [C_0402NEW]  109.56 41.31 270 top
PC501  -  [C_0402NEW]  110.45 41.31 270 top
PC502  -  [C_0805NEW]  111.76 41.47 270 top
PC503  -  [C_0805NEW]  113.46 41.47 270 top
PC504  -  [C_0603NEW]  126.36 42.63 180 top
PC505  -  [C_0402NEW]  127.93 49.65 90 top
PC506  -  [C_0603NEW]  123.95 42.63 180 top
PC507  -  [C_0402NEW]  132.52 33.44 180 top
PC508  -  [C_0402NEW]  119.44 49.62 270 bottom
PC509  -  [C_0402NEW]  124.72 51.65 180 top
PC510  -  [C_0402NEW]  126.17 50.58 270 top
PC511  -  [C_0402NEW]  132.52 34.33 180 top
PC600  -  [C_0603NEW]  111.65 84.54 270 top
PC601  -  [C_0603NEW]  112.87 83.13 90 top
PC602  -  [C_0603NEW]  108.07 81.37 180 top
PC603  -  [C_0402NEW]  105.8 81.24 180 top
PC604  -  [C_0805NEW]  95.42 80.32 0 bottom
PC605  -  [C_0805NEW]  96.02 85.2 270 top
PC606  -  [C_0402NEW]  103.56 84.15 90 top
PC607  -  [C_0805NEW]  101.35 85.2 270 top
PC608  -  [C_0805NEW]  95.42 80.32 0 top
PC609  -  [C_0402NEW]  102.67 84.15 90 top
PC610  -  [C_0805NEW]  97.8 85.2 270 top
PC611  -  [C_0805NEW]  99.57 85.2 270 top
PC612  -  [C_0402NEW]  111.88 82.25 270 top
PC613  -  [C_0402NEW]  112.77 81.33 90 top
PC614  -  [C_0805NEW]  114.5 82.63 270 bottom
PC615  -  [C_0805NEW]  116.2 82.63 270 bottom
PC616  -  [C_0402NEW]  111 80.85 90 top
PC617  -  [C_0402NEW]  111 78.05 90 top
PC618  -  [C_0402NEW]  110.11 81.76 270 top
PC619  -  [C_0402NEW]  109.66 85.4 270 top
PC700  -  [C_0402NEW]  21.77 82.51 270 top
PC701  -  [C_0402NEW]  18.68 79.97 180 bottom
PC702  -  [C_0402NEW]  17.79 84.19 270 top
PC703  -  [C_0402NEW]  17.76 80.61 0 top
PC704  -  [C_0805NEW]  19.2 58.89 180 top
PC705  -  [C_0805NEW]  19.2 60.67 180 top
PC706  -  [C_0402NEW]  18.68 83.27 90 top
PC707  -  [C_0402NEW]  17.76 82.41 0 top
PC708  -  [C_0402NEW]  18.73 81.83 270 bottom
PC709  -  [C_0805NEW]  19.2 62.45 180 top
PC710  -  [C_0402NEW]  20.77 84.9 0 bottom
PC711  -  [C_0402NEW]  21.57 85.05 0 top
PC712  -  [C_0402NEW]  19.57 83.27 90 top
PC713  -  [C_0603NEW]  18.7 77.72 270 bottom
PC714  -  [C_0402NEW]  20.71 85.94 180 top
PC715  -  [C_0402NEW]  18.63 73.06 0 top
PC717  -  [C_0603NEW]  25.71 83.53 270 top
PC718  -  [C_0603NEW]  24.06 76.99 90 top
PC719  -  [C_0603NEW]  21.65 76.99 90 top
PC728  -  [C_0402NEW]  28 77.94 90 top
PC729  -  [C_0402NEW]  28 79.13 90 bottom
PC730  -  [C_0402NEW]  28.89 78.96 0 bottom
PC733  -  [C_0402NEW]  26.47 80.1 180 top
PC734  -  [C_0805NEW]  30.93 61.14 0 top
PC735  -  [C_0805NEW]  30.93 59.41 0 top
PC736  -  [C_0805NEW]  30.93 62.92 0 top
PC737  -  [C_0402NEW]  29.8 80.84 270 top
PC738  -  [C_0402NEW]  26.47 80.99 180 top
PC739  -  [C_0402NEW]  27.88 80.34 0 top
PC740  -  [C_0603NEW]  26.35 76.1 270 bottom
PC741  -  [C_0402NEW]  27.92 82.77 0 top
PC742  -  [C_0402NEW]  27.92 81.88 0 top
PC743  -  [C_0402NEW]  28.68 84.54 0 bottom
PC744  -  [C_0402NEW]  27.57 72.66 0 top
PC745  -  [C_0402NEW]  29.78 82.69 90 bottom
PC746  -  [C_0402NEW]  28.84 80.99 180 bottom
PC747  -  [C_0402NEW]  16.95 64.68 270 top
PC748  -  [C_0402NEW]  17.13 66.97 90 top
PC749  -  [C_0402NEW]  30.87 57.21 0 top
PC750  -  [C_0402NEW]  30.87 58.1 0 top
PC850  -  [C_0805NEW]  44.75 71.75 90 top
PC851  -  [C_0805NEW]  42.84 71.75 90 top
PC852  -  [C_0805NEW]  45.34 66.86 270 bottom
PC853  -  [C_0805NEW]  45.29 66.86 270 top
PC854  -  [C_0805NEW]  44.75 71.75 90 bottom
PC855  -  [C_0805NEW]  43.43 66.86 270 bottom
PC856  -  [C_0805NEW]  42.84 71.75 90 bottom
PC858  -  [C_0805NEW]  61.8 83.26 90 top
PC859  -  [C_0805NEW]  63.7 83.26 90 top
PC860  -  [C_0805NEW]  67.51 83.26 90 top
PC861  -  [C_0805NEW]  65.03 72.75 270 top
PC862  -  [C_0805NEW]  71.32 83.26 90 top
PC890  -  [C_0805NEW]  66.93 72.72 270 top
PC891  -  [C_0805NEW]  70.74 72.75 270 top
PC892  -  [C_0805NEW]  68.84 72.72 270 top
PC893  -  [C_0805NEW]  69.42 83.26 90 top
PC894  -  [C_0805NEW]  63.12 72.75 270 top
PC900  -  [C_0402NEW]  191.55 81.57 270 top
PC901  -  [C_0402NEW]  192.44 81.57 270 top
PC902  -  [C_0402NEW]  184 71.29 270 bottom
PC903  -  [C_0402NEW]  183.09 71.29 270 bottom
PC904  -  [C_0402NEW]  123.12 31.92 270 top
PC905  -  [C_0402NEW]  121.34 31.92 270 top
PC906  -  [C_0402NEW]  130.36 19.98 270 bottom
PC907  -  [C_0402NEW]  131.25 19.98 270 bottom
PC908  -  [C_0603NEW]  187.37 83.2 180 top
PC909  -  [C_0402NEW]  177.43 80.48 180 top
PC910  -  [C_0402NEW]  184.79 78.04 180 top
PC911  -  [C_0402NEW]  123.25 27.33 180 top
PC913  -  [C_0805NEW]  61.22 72.75 270 top
PC914  -  [C_0805NEW]  59.89 83.26 90 top
PC915  -  [C_0805NEW]  65.61 83.26 90 top
PC916  -  [C_0805NEW]  57.99 83.26 90 top
PC980  -  [C_B]  68.73 84.42 0 bottom
PC981  -  [C_B]  62.39 23.62 270 bottom
PC984  -  [C_B]  65.14 84.43 180 bottom
PC986  -  [C_B]  55.79 84.43 0 bottom
PC987  -  [C_D2E]  34.86 63.95 90 bottom
PC990  -  [C_B]  104.68 43.69 270 bottom
PC991  -  [C_B]  100.82 44.32 270 bottom
PC993  -  [C_B]  52.18 84.43 180 bottom
PC994  -  [C_D2E]  37.01 57.26 270 bottom
PC995  -  [C_B]  97.34 43.81 270 bottom
PC1225  -  [C_0402NEW]  55.57 84.23 90 top
PC1226  -  [C_0402NEW]  54.68 84.23 90 top
PC1227  -  [C_0402NEW]  56.46 84.23 90 top
PC1228  -  [C_0402NEW]  64.83 77.24 0 top
PC1229  -  [C_0402NEW]  68 79.78 0 top
PC1230  -  [C_0402NEW]  68.97 78.49 0 top
PC1231  -  [C_0402NEW]  65.66 74.19 90 top
PC1232  -  [C_0402NEW]  64.7 78.51 0 top
PC1233  -  [C_0402NEW]  62.29 77.75 0 top
PC1234  -  [C_0402NEW]  64.01 74.24 90 top
PC1235  -  [C_0402NEW]  63.12 74.24 90 top
PC1236  -  [C_0402NEW]  68.46 74.19 90 top
PC1237  -  [C_0402NEW]  69.35 74.19 90 top
PC1238  -  [C_0402NEW]  67.16 78.51 0 top
PC1239  -  [C_0402NEW]  68.66 77.11 180 top
PC1240  -  [C_0402NEW]  67.44 74.19 90 top
PC1256  -  [C_0603NEW]  48.19 66.57 270 bottom
PC1257  -  [C_0603NEW]  48.19 66.57 270 top
PC1258  -  [C_0603NEW]  46.29 72.8 90 top
PC1259  -  [C_0603NEW]  47.56 72.8 90 top
PC1260  -  [C_0603NEW]  46.92 66.57 270 bottom
PC1261  -  [C_0603NEW]  46.92 66.57 270 top
PC1262  -  [C_0603NEW]  101.21 45.71 180 top
PC1263  -  [C_0603NEW]  101.21 46.9 180 top
PC1264  -  [C_0603NEW]  101.21 48.09 180 top
PC1265  -  [C_0603NEW]  103.7 67.34 180 top
PC1266  -  [C_0603NEW]  104.93 64.92 270 top
PC1267  -  [C_0603NEW]  85.66 66.57 90 top
PC1268  -  [C_0603NEW]  58.95 66.08 0 top
PC1269  -  [C_0603NEW]  57.02 64.73 180 top
PC1270  -  [C_0603NEW]  101.21 49.29 180 top
PC1271  -  [C_0603NEW]  100.13 54.89 270 top
PC1272  -  [C_0603NEW]  71.38 64.99 90 top
PC1273  -  [C_0603NEW]  58.75 67.35 90 top
PC1285  -  [C_0402NEW]  57.6 68.76 270 top
PC1286  -  [C_0402NEW]  49.15 73.1 90 bottom
PC1287  -  [C_0402NEW]  53.14 73.04 90 top
PC1288  -  [C_0402NEW]  48.7 73.04 90 top
PC1289  -  [C_0402NEW]  49.26 66.52 270 top
PC1290  -  [C_0402NEW]  47.38 73.1 90 bottom
PC1291  -  [C_0402NEW]  49.26 66.52 270 bottom
PC1292  -  [C_0402NEW]  52.25 73.04 90 top
PC1293  -  [C_0402NEW]  50.48 73.04 90 top
PC1294  -  [C_0402NEW]  51.37 73.04 90 top
PC1295  -  [C_0402NEW]  48.27 73.1 90 bottom
PC1296  -  [C_0402NEW]  49.59 73.04 90 top
PC1297  -  [C_0402NEW]  76.05 69.86 0 top
PC1298  -  [C_0402NEW]  104.96 47 90 top
PC1299  -  [C_0402NEW]  103.18 47 90 top
PC1300  -  [C_0402NEW]  101.91 62.24 90 top
PC1301  -  [C_0402NEW]  70.24 66.27 270 top
PC1302  -  [C_0402NEW]  102.29 47 90 top
PC1303  -  [C_0402NEW]  72.45 69.49 0 top
PC1304  -  [C_0402NEW]  73.21 67.84 0 top
PC1305  -  [C_0402NEW]  73.79 64.59 90 top
PC1306  -  [C_0402NEW]  72.9 65.48 90 top
PC1307  -  [C_0402NEW]  74.68 65.35 90 top
PC1308  -  [C_0402NEW]  72.85 64.03 180 top
PC1309  -  [C_0402NEW]  69.35 65.51 270 top
PC1310  -  [C_0402NEW]  60.26 64.81 270 top
PC1311  -  [C_0402NEW]  57.6 66.07 90 top
PC1312  -  [C_0402NEW]  59.37 64.81 270 top
PC1313  -  [C_0402NEW]  58.48 64.81 270 top
PC1314  -  [C_0402NEW]  86.8 66.76 90 top
PC1315  -  [C_0402NEW]  98.36 42.99 270 top
PC1316  -  [C_0402NEW]  74.12 70.51 180 top
PC1317  -  [C_0402NEW]  75.19 70.71 270 top
PC1318  -  [C_0402NEW]  75.89 65.21 0 top
PC1319  -  [C_0402NEW]  104.07 47 90 top
PC1320  -  [C_0402NEW]  100.01 62.01 270 top
PC1321  -  [C_0402NEW]  101.55 65.05 180 top
PC1322  -  [C_0402NEW]  75.88 68.35 0 top
PC1323  -  [C_0402NEW]  99.24 42.99 270 top
PC1900  -  [C_D2E]  37.27 75.52 90 bottom
PC1901  -  [C_D2E]  32.57 75.52 90 bottom
PC1903  -  [C_D2E]  39.55 65.72 90 bottom
PC1908  -  [C_0805NEW]  21.04 58.59 0 top
PC1909  -  [C_0805NEW]  30.92 56.02 270 top
PC1910  -  [C_0402NEW]  29.51 23.52 0 bottom
PC1911  -  [C_0603NEW]  205.95 57.98 270 top
PC1912  -  [C_0805NEW]  200.53 69.35 270 top
PC1913  -  [C_0805NEW]  202.28 69.35 270 top
PC1914  -  [C_0402NEW]  126.14 33.24 270 top
PC1915  -  [C_0402NEW]  127.69 30.84 0 top
PC1916  -  [C_0402NEW]  127.73 29.57 0 top
PC1917  -  [C_0805NEW]  29.01 52.04 0 top
PC1918  -  [C_0603NEW]  192.31 67.61 90 top
PC1919  -  [C_0402NEW]  199.16 57.63 0 bottom
PC1920  -  [C_0402NEW]  193.72 57.81 0 bottom
PC1921  -  [C_D2]  197.38 71.25 0 bottom
PD5  -  [D_EC31QS04]  113.09 38.01 0 bottom
PD9  -  [BAS40CW_SOT323-3]  152.37 33.21 90 top
PD10  -  [RB751V-40_SOD323-2]  147.81 44.26 0 top
PD11  -  [GLZ5P1B_LL34-2]  143.95 40.98 180 bottom
PD200  -  [BZT52-B5V6S_SOD323-2]  188.15 55.97 180 bottom
PD901  -  [BAV99W-7-F_SOT323-3]  187.14 81.8 180 top
PD902  -  [TP0610K-T1-E3_SOT23-3]  195.13 78.09 180 top
PD903  -  [RB751V-40_SOD323-2]  187.15 75.18 180 top
PD904  -  [TP0610K-T1-E3_SOT23-3]  125.53 22.59 180 top
PD905  -  [TP0610K-T1-E3_SOT23-3]  130.49 22.59 180 top
PD906  -  [RB751V-40_SOD323-2]  190.73 75.2 180 top
PD907  -  [RB751V-40_SOD323-2]  188.59 73.51 0 top
PD909  -  [RB751V-40_SOD323-2]  202.32 55.51 90 top
PH700  -  [R_0402NEW]  23.55 70.57 0 top
PH701  -  [R_0402NEW]  17.96 70.37 90 bottom
PH702  -  [R_0402NEW]  26.22 70.57 180 top
PH703  -  [R_0402NEW]  24.39 60.22 0 bottom
PH901  -  [R_0402NEW]  72.19 70.37 90 top
PJP200  -  [JUMP_43X118]  196.98 68.47 90 top
PJP201  -  [JUMP_43X79]  207.19 69.73 270 bottom
PJP202  -  [JUMP_43X79]  181.46 68.06 180 bottom
PJP203  -  [JUMP_43X79]  211 69.73 270 bottom
PJP204  -  [JUMP_43X79]  181.46 64.25 180 bottom
PJP205  -  [JUMP_43X118]  192.72 70.51 180 bottom
PJP301  -  [JUMP_43X79]  46.07 21.42 180 bottom
PJP303  -  [JUMP_43X118]  65.5 23.56 0 bottom
PJP400  -  [JUMP_43X79]  107.84 48.98 0 bottom
PJP401  -  [JUMP_43X79]  170.11 36.88 270 bottom
PJP402  -  [JUMP_43X79]  91.71 51.14 0 bottom
PJP403  -  [JUMP_43X79]  157.24 38.95 0 bottom
PJP500  -  [JUMP_43X79]  116.73 39.76 90 top
PJP501  -  [JUMP_43X118]  106.71 48.11 0 top
PJP502  -  [JUMP_43X118]  106.71 42.78 0 top
PJP507  -  [JUMP_43X79]  136.49 40.86 270 top
PJP508  -  [JUMP_43X79]  140.33 40.86 270 top
PJP600  -  [JUMP_43X79]  119.78 81.37 0 bottom
PJP601  -  [JUMP_43X118]  95.34 83.97 0 bottom
PJP700  -  [JUMP_43X118]  19.34 55.32 90 top
PJP701  -  [JUMP_43X118]  27.44 55.47 90 top
PJP702  -  [JUMP_43X39]  176.82 82.05 90 top
PL201  -  [TOKO_FDSD0630-H-2R2M-P3_2P]  197.54 61.94 0 bottom
PL400  -  [TAIYO_NRS4018T1R0NDGJ_2P]  101.79 50.25 180 bottom
PL401  -  [TAIYO_NRS4018T1R0NDGJ_2P]  166.55 39.08 180 bottom
PL600  -  [TOKO_FDVE0630-H-R47M-P3_2P]  105.49 82.98 180 bottom
PL701  -  [TOKO_FDUE0640J-H_4P]  21.27 60.6 90 bottom
PL704  -  [TOKO_FDUE0640J-H_4P]  28.76 70.64 270 bottom
PL900  -  [L_1812-1806]  189.3 75.73 180 bottom
PL901  -  [MURAT_BLM18BD102SN1D_L0603_2P]  192.16 82.53 90 top
PL902  -  [L_1812-1806]  126.55 39.15 0 bottom
PL903  -  [L_1812-1806]  190.02 70.57 0 bottom
PL1207  -  [TOKO_FDSD0630-H-3R3M-P3_2P]  192.18 66.01 270 bottom
PL1210  -  [TOKO_FDSD0630-H-1R0M-P3_2P]  55.37 22.08 180 bottom
PL1211  -  [TOKO_FDSD0630-H-3R3M-P3_2P]  135.67 30.46 90 bottom
PL1212  -  [TOKO_FDSD0630-H-1R0M-P3_2P]  116.07 43.14 180 bottom
PQ7  -  [SSM3K7002FU_SC70-3]  151.06 40.79 0 top
PQ101  -  [FDMS6673BZ_POWER56-8-5]  156.9 37.43 270 top
PQ102  -  [FDMS6673BZ_POWER56-8-5]  162.26 39.2 90 top
PQ103  -  [AO4407AL_SO8]  118.99 37.33 90 bottom
PQ204  -  [DMN66D0LDW-7_SOT363-6]  197.48 55.32 90 bottom
PQ900  -  [FDV301N_NL_SOT23-3]  194.88 84.57 180 top
PQ901  -  [RHU002N06_SOT323-3]  189.77 82.5 180 top
PQ903  -  [TP0610K-T1-E3_SOT23-3]  179.89 80.76 0 top
PQ904  -  [SSM3K7002FU_SC70-3]  184.55 82.46 180 top
PQ908  -  [SSM3K7002FU_SC70-3]  38.59 82.03 90 top
PQ1207  -  [AON7406L_DFN8-5]  193.31 62.7 270 top
PQ1208  -  [AON7212L_DFN8-5]  187.65 61.43 270 top
PQ1209  -  [AON7406L_DFN8-5]  200.51 60.74 90 top
PQ1210  -  [AON7212L_DFN8-5]  204.95 60.69 90 top
PQ1211  -  [SIR472DP-T1-GE3_POWERPAK8-5]  114.99 48.22 180 top
PQ1215  -  [AON7406L_DFN8-5]  50.58 22.61 180 top
PQ1217  -  [AON6920_DFN5X6A-8-10]  18.22 68.9 270 top
PQ1218  -  [AON6920_DFN5X6A-8-10]  32.14 65.24 90 top
PQ1219  -  [SIR818DP-T1_POWERPAK-SO8-5]  121.22 48.61 180 top
PQ1221  -  [SIR818DP-T1_POWERPAK-SO8-5]  139.12 28.05 90 top
PQ1223  -  [SIR472DP-T1-GE3_POWERPAK8-5]  139.12 33.52 90 top
PQ1226  -  [FDMC7672S_MLP8-5]  52.15 19.74 0 top
PQ1227  -  [SSM3K7002FU_SC70-3]  183.48 64.47 0 top
PQ1228  -  [DMN66D0LDW-7_SOT363-6]  189.29 68.75 270 top
PR13  -  [R_1206_4P-D]  155.02 40.82 270 top
PR14  -  [R_0402NEW]  142.71 39.97 0 top
PR15  -  [R_0402NEW]  142.71 39.08 0 top
PR16  -  [R_0402NEW]  162.27 44.35 0 top
PR17  -  [R_0402NEW]  155.61 34.35 270 top
PR18  -  [R_0402NEW]  145.83 41.86 270 bottom
PR19  -  [R_0402NEW]  192.54 57.71 270 bottom
PR20  -  [R_0402NEW]  161.37 44.35 90 top
PR22  -  [R_0402NEW]  154.72 33.4 90 top
PR23  -  [R0402_0OHM-NEW]  144.3 38.32 180 bottom
PR24  -  [R_0805NEW]  144.13 41.36 0 top
PR25  -  [R_1206_4P-D]  125.67 35.12 0 top
PR26  -  [R_1206NEW]  131.53 27.9 90 top
PR28  -  [R_0402NEW]  147.25 41.14 90 top
PR29  -  [R_0402NEW]  148.57 31.65 90 top
PR30  -  [R0402_0OHM-NEW]  149.46 32.57 270 top
PR31  -  [R_0402NEW]  150.09 41.86 270 bottom
PR32  -  [R_0603NEW]  147.52 35.83 0 top
PR33  -  [R_0402NEW]  148.7 41.21 90 top
PR34  -  [R_0402NEW]  148.17 42.99 180 top
PR35  -  [R0402_0OHM-NEW]  149.6 39.73 180 top
PR36  -  [R_0402NEW]  151.87 41.86 270 bottom
PR37  -  [R_0402NEW]  151.64 39.97 0 bottom
PR38  -  [R_0402NEW]  152.24 35.45 0 bottom
PR40  -  [R_0402NEW]  152.47 36.08 270 top
PR41  -  [R_0402NEW]  152.94 41.98 90 top
PR43  -  [R_0402NEW]  190.27 57.87 180 bottom
PR44  -  [R_0402NEW]  110.8 48.89 90 bottom
PR45  -  [R_0402NEW]  168.33 39.43 270 top
PR46  -  [R0402_0OHM-NEW]  150.71 33.61 270 bottom
PR47  -  [R_0402NEW]  122.23 30.95 90 top
PR48  -  [R_0402NEW]  27.27 21.35 0 bottom
PR49  -  [R_0402NEW]  153.36 36.08 270 top
PR104  -  [R_0402NEW]  152.12 36.33 0 bottom
PR119  -  [R0603_0OHM-NEW]  34.98 22.19 0 top
PR120  -  [R0603_0OHM-NEW]  32.32 25.23 180 top
PR200  -  [R_0402NEW]  189.35 58.22 0 top
PR201  -  [R_0402NEW]  197.16 57.67 90 top
PR202  -  [R_0402NEW]  191.63 56.82 90 bottom
PR203  -  [R_0402NEW]  195.54 57.95 270 bottom
PR206  -  [R_0603NEW]  186.81 55.77 90 top
PR207  -  [R_0603NEW]  197.61 56.1 0 top
PR208  -  [R_1206NEW]  189.54 62.89 90 top
PR209  -  [R_1206NEW]  202.31 64.48 0 top
PR210  -  [R_0402NEW]  184.89 55.93 270 top
PR211  -  [R_0402NEW]  184.02 56.3 270 top
PR212  -  [R_0402NEW]  192.41 55 90 bottom
PR216  -  [R_0402NEW]  193.72 56.92 0 bottom
PR218  -  [R_0402NEW]  198.32 57.65 180 bottom
PR219  -  [R0402_0OHM-NEW]  185.76 55.02 90 top
PR300  -  [R_0603NEW]  36.38 20.81 180 top
PR301  -  [R_0402NEW]  28.76 19.06 0 top
PR302  -  [R_1206NEW]  55.7 22.03 0 top
PR303  -  [R_0603NEW]  26.25 19.19 0 top
PR304  -  [R_0402NEW]  28.34 24.02 90 top
PR305  -  [R_0402NEW]  27.29 21.35 0 top
PR306  -  [R0402_0OHM-NEW]  27.26 22.31 0 bottom
PR307  -  [R_0402NEW]  25.97 23.58 180 top
PR308  -  [R_0402NEW]  27.26 23.18 0 top
PR323  -  [R_0402NEW]  27.26 24.04 0 bottom
PR400  -  [R_1206NEW]  100.32 47.08 180 bottom
PR401  -  [R_0402NEW]  105.26 52.54 0 top
PR402  -  [R0402_0OHM-NEW]  102.98 54.95 180 top
PR403  -  [R_0402NEW]  102.09 53.05 0 top
PR404  -  [R_0402NEW]  107.04 51.52 0 top
PR405  -  [R0402_0OHM-NEW]  170.31 43.65 180 top
PR406  -  [R_1206NEW]  166.43 38.38 90 top
PR407  -  [R_0402NEW]  169.4 42.76 0 top
PR408  -  [R_0402NEW]  171.16 40.09 0 top
PR409  -  [R_0402NEW]  172.09 40.98 180 top
PR500  -  [R_0402NEW]  128.12 47.59 0 top
PR501  -  [R_0603NEW]  127.95 43.97 270 top
PR502  -  [R_0402NEW]  129.04 48.48 180 top
PR503  -  [R0402_0OHM-NEW]  128.82 50.57 270 top
PR504  -  [R_1206NEW]  117.99 47.8 90 bottom
PR505  -  [R_0402NEW]  122.61 49.67 90 top
PR506  -  [R_0402NEW]  125.58 51.65 0 top
PR507  -  [R_0402NEW]  125.28 50.58 270 top
PR508  -  [R0402_0OHM-NEW]  124.39 49.67 90 top
PR509  -  [R0402_0OHM-NEW]  123.5 50.58 270 top
PR510  -  [R_0402NEW]  127.04 50.57 270 top
PR512  -  [R0402_0OHM-NEW]  195.99 54.04 180 bottom
PR513  -  [R0402_0OHM-NEW]  188.83 78.45 0 top
PR514  -  [R_0402NEW]  192.77 54.06 0 bottom
PR515  -  [R_0402NEW]  193.3 54.93 0 bottom
PR516  -  [R0402_0OHM-NEW]  189.34 56.98 0 bottom
PR517  -  [R0402_0OHM-NEW]  102.55 51.98 270 top
PR518  -  [R0402_0OHM-NEW]  168.33 41.19 270 top
PR521  -  [R0402_0OHM-NEW]  27.44 20.24 0 top
PR600  -  [R_0402NEW]  110.55 85.4 270 top
PR601  -  [R_0402NEW]  114.79 82 90 top
PR602  -  [R_0402NEW]  108.77 85.4 270 top
PR603  -  [R_0402NEW]  111.45 85.46 0 top
PR604  -  [R0402_0OHM-NEW]  107.88 85.38 270 top
PR605  -  [R_0603NEW]  106.67 82.64 0 top
PR606  -  [R_1206NEW]  105.53 82.77 180 top
PR607  -  [R_0402NEW]  109.23 81.76 270 top
PR608  -  [R_0402NEW]  109.23 78.05 90 top
PR609  -  [R_0402NEW]  110.11 78.97 270 top
PR610  -  [R0402_0OHM-NEW]  108.34 78.05 90 top
PR611  -  [R0402_0OHM-NEW]  115.68 82 90 top
PR700  -  [R_0402NEW]  20.89 82.51 270 top
PR701  -  [R_0402NEW]  24.26 85.94 180 top
PR702  -  [R_0402NEW]  17.76 81.5 0 top
PR703  -  [R_0402NEW]  17.79 80.94 90 bottom
PR704  -  [R_0402NEW]  24.26 85.05 180 top
PR705  -  [R_0402NEW]  16.87 80.63 90 top
PR706  -  [R_0402NEW]  21.57 85.94 0 top
PR707  -  [R_0402NEW]  19.79 85.05 0 top
PR708  -  [R_0402NEW]  20.76 80.73 0 top
PR709  -  [R_0402NEW]  20.78 85.79 0 bottom
PR710  -  [R_0603NEW]  20.54 75.22 180 bottom
PR711  -  [R_1206NEW]  21.46 70.95 180 top
PR712  -  [R_0402NEW]  19.87 85.88 270 bottom
PR714  -  [R_0603NEW]  18.87 83.1 180 bottom
PR715  -  [R_0402NEW]  17.76 84.14 0 bottom
PR716  -  [R_0402NEW]  17.76 79.72 0 top
PR717  -  [R_0402NEW]  25.08 85.92 270 bottom
PR719  -  [R_0402NEW]  23.5 85.92 270 bottom
PR720  -  [R0402_0OHM-NEW]  22.61 85.92 270 bottom
PR721  -  [R0402_0OHM-NEW]  24.44 75.2 90 bottom
PR722  -  [R0603_0OHM-NEW]  22.03 76.1 270 bottom
PR723  -  [R0402_0OHM-NEW]  26.85 85.92 270 bottom
PR724  -  [R_0603NEW]  23.3 76.1 270 bottom
PR725  -  [R_0402NEW]  25.97 85.92 270 bottom
PR726  -  [R_0402NEW]  26.75 85.89 180 top
PR727  -  [R_0402NEW]  26.75 84.98 180 top
PR728  -  [R_0402NEW]  28.89 78.07 0 bottom
PR733  -  [R_0402NEW]  28.89 77.94 0 top
PR734  -  [R_0402NEW]  26.55 78.35 180 top
PR736  -  [R0402_0OHM-NEW]  29.6 85.43 180 bottom
PR737  -  [R_0402NEW]  29.78 78.83 180 top
PR738  -  [R_0402NEW]  29.8 80.02 180 bottom
PR740  -  [R_0402NEW]  26.55 79.21 180 top
PR741  -  [R_0402NEW]  27.87 83.71 90 top
PR742  -  [R_0603NEW]  27.74 76.61 270 bottom
PR743  -  [R_1206NEW]  30.16 71.2 180 top
PR744  -  [R_0402NEW]  28.84 83.65 0 top
PR747  -  [R_0603NEW]  28.82 85.43 0 top
PR748  -  [R_0402NEW]  28.51 83.48 270 bottom
PR749  -  [R_0402NEW]  30.66 82.69 90 top
PR750  -  [R_0402NEW]  29.78 81.85 270 bottom
PR900  -  [R_0402NEW]  193.67 80.75 0 top
PR901  -  [R_0402NEW]  197.31 81.09 0 top
PR902  -  [R_0402NEW]  195.45 80.75 0 top
PR903  -  [R_0402NEW]  193.28 78.93 90 top
PR904  -  [R_0402NEW]  190.49 83.62 180 top
PR905  -  [R_0402NEW]  128.16 66.26 180 top
PR906  -  [R_0402NEW]  195.08 79.82 180 top
PR908  -  [R_0402NEW]  182.51 83.63 0 top
PR909  -  [R_0402NEW]  183.42 82.77 180 top
PR910  -  [R_0402NEW]  182.25 79.46 180 top
PR911  -  [R0402_0OHM-NEW]  183.17 79.36 0 top
PR913  -  [R_0402NEW]  125.08 24.35 0 top
PR915  -  [R_0402NEW]  121.34 24.6 90 top
PR916  -  [R_0402NEW]  122.23 25.51 270 top
PR917  -  [R_0402NEW]  127.95 20.51 90 top
PR918  -  [R0402_0OHM-NEW]  124.01 23.38 90 top
PR935  -  [R_0402NEW]  30.84 46.96 270 bottom
PR936  -  [R0402_0OHM-NEW]  124.24 26.44 0 top
PR937  -  [R_0402NEW]  125.15 27.33 180 top
PR938  -  [R_0402NEW]  183.95 76.37 270 top
PR939  -  [R_0603NEW]  17.33 71.92 270 top
PR940  -  [R_0603NEW]  33.46 66.33 270 top
PR941  -  [R_0402NEW]  198.94 57.27 90 top
PR942  -  [R_1206NEW]  185.85 67.91 270 top
PR943  -  [R_0402NEW]  183.33 67.75 0 top
PR954  -  [R0402_0OHM-NEW]  187.71 71.27 90 top
PR955  -  [R0402_0OHM-NEW]  154.82 37.21 270 bottom
PR956  -  [R0402_0OHM-NEW]  153.93 37.21 270 bottom
PR957  -  [R_0402NEW]  203.58 57.67 270 top
PR958  -  [R_0402NEW]  204.9 57.72 270 top
PR959  -  [R_0402NEW]  123.96 29.77 270 top
PR960  -  [R_0402NEW]  125.23 32.32 90 top
